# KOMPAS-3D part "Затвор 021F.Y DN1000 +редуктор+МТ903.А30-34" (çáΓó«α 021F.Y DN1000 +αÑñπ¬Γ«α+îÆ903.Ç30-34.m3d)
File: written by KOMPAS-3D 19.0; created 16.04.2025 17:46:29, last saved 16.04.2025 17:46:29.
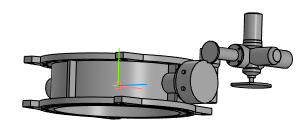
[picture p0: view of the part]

Document properties: Полное имя файла: Затвор 021F.Y DN1000 +редуктор+МТ903.А30-34.a3d

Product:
- Part/product: Затвор 021F.Y DN1000 +редуктор+МТ903.А30-34
    Масса: 1197.56

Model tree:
1. Операция без истории:1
